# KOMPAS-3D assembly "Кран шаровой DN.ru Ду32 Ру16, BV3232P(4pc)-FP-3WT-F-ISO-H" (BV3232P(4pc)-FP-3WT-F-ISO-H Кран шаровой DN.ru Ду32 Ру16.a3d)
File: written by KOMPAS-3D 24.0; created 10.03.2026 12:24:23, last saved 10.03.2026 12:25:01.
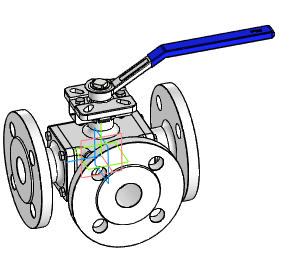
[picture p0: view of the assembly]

Document properties: Автор: R2D2; Полное имя файла: E:\Работа\Зайцев\BV3232P(4pc)-FP-3WT-F-ISO-H Кран шаровой DN.ru Ду15-100 Ру16\DN32\исходные материалы\BV3232P(4pc)-FP-3WT-F-ISO-H Кран шаровой DN.ru Ду32 Ру16.a3d

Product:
- Component [assembly]: Сборка1  | qty 1  | pos. 1  | Автор: R2D2; source file: dn32_3d_step.a3d
- Part/product: Кран шаровой DN.ru Ду32 Ру16  | designation BV3232P(4pc)-FP-3WT-F-ISO-H
    Масса: 9.3
    Раздел спецификации: Прочие изделия
    Примечание: D160-36349

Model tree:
1. Эскиз:1  (labels: Грань.Твердое тело1; Ребро.Твердое тело1)
2. Элемент выдавливания:1  (labels: Грань.Твердое тело1; Твердое тело1)
     Расстояние 2 = 0.01

Referenced files in E:\Работа\Зайцев\BV3232P(4pc)-FP-3WT-F-ISO-H Кран шаровой DN.ru Ду15-100 Ру16\DN32\исходные материалы\: dn32_3d_step.a3d
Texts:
  BV3232P(4pc)-FP-3WT-F-ISO-H
  Сборка1 Сборка1
  Ось Z.Начало координат
  Ось Y.Начало координат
